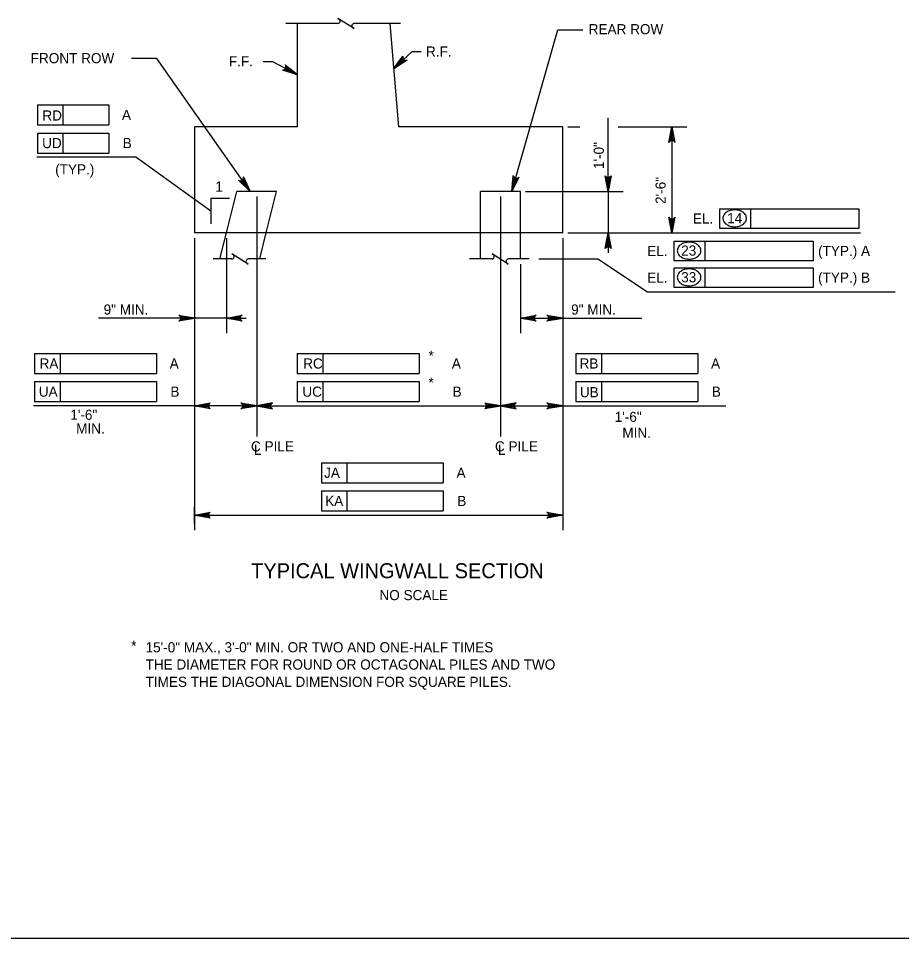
# Model space of a CAD drawing. Extents: x 638340 to 640242, y 295465 to 298435.
# Drawn here: x 639639.2 to 639900.6, y 296074.5 to 296346.9 of the extents above; entities that cross this region are included whole.
import ezdxf

# ---------------------------------------------------------------- set-up
doc = ezdxf.new("R2010")
doc.units = 0
for name, color, linetype in [('2', 7, 'Continuous'), ('4', 7, 'Continuous'), ('Level 2', 7, 'Continuous'), ('Level 4', 7, 'Continuous'), ('Level 5', 7, 'Continuous')]:
    doc.layers.add(name, color=color, linetype=linetype)

msp = doc.modelspace()

# ---------------------------------------------------------------- linework, layer by layer
at = {"layer": '2'}
msp.add_line((640102.46, 296074.46), (639316.46, 296074.46), dxfattribs=at)
at = {"layer": 'Level 2'}
for p, q in [((639798.82, 296343.48), (639806.3, 296343.48)), ((639750.26, 296331.93), (639755.72, 296337.09)), ((639755.72, 296337.09), (639758.45, 296337.09)), ((639680.15, 296334.99), (639672.65, 296334.99)), ((639714.53, 296334.05), (639711.68, 296334.05)), ((639721.87, 296330.24), (639714.53, 296334.05)), ((639644.86, 296321.27), (639665.95, 296321.27)), ((639644.86, 296321.27), (639644.86, 296315.38)), ((639652.41, 296321.27), (639652.41, 296315.38)), ((639665.95, 296321.27), (639665.95, 296315.38)), ((639644.86, 296315.38), (639665.95, 296315.38)), ((639813.74, 296295.66), (639813.74, 296317.49)), ((639644.86, 296312.93), (639644.86, 296307.04)), ((639644.86, 296312.93), (639665.95, 296312.93)), ((639652.41, 296312.93), (639652.41, 296307.04)), ((639665.95, 296312.93), (639665.95, 296307.04)), ((639801.84, 296314.82), (639805.36, 296314.82)), ((639816.72, 296314.82), (639837.05, 296314.82)), ((639832.62, 296314.82), (639832.62, 296283.39)), ((639644.86, 296307.04), (639665.95, 296307.04)), ((639673.99, 296305.77), (639644.7, 296305.77)), ((639696.17, 296289.84), (639673.99, 296305.77)), ((639696.17, 296293.58), (639696.17, 296286.1)), ((639701.71, 296293.58), (639696.17, 296293.58)), ((639709.75, 296294.13), (639709.75, 296223.13)), ((639709.75, 296294.13), (639709.75, 296223.13)), ((639781.88, 296294.13), (639781.88, 296223.13)), ((639789.31, 296295.66), (639818.16, 296295.66)), ((639813.74, 296295.66), (639813.74, 296283.39)), ((639846.84, 296290.56), (639887.97, 296290.56)), ((639846.84, 296284.66), (639846.84, 296290.56)), ((639855.99, 296284.66), (639855.99, 296290.56)), ((639887.97, 296290.56), (639887.97, 296284.66)), ((639801.84, 296283.39), (639888.44, 296283.39)), ((639801.84, 296283.39), (639818.16, 296283.39)), ((639813.74, 296283.39), (639813.74, 296277.49)), ((639887.97, 296284.66), (639846.84, 296284.66)), ((639691.35, 296281.85), (639691.35, 296219.14)), ((639691.35, 296281.85), (639691.35, 296195.4)), ((639691.35, 296281.85), (639691.35, 296253.75)), ((639700.79, 296281.85), (639700.79, 296253.75)), ((639800.3, 296281.85), (639800.3, 296219.14)), ((639800.3, 296281.85), (639800.3, 296195.4)), ((639800.3, 296281.85), (639800.3, 296253.75)), ((639833.33, 296275.08), (639833.33, 296280.97)), ((639833.33, 296280.97), (639874.46, 296280.97)), ((639842.49, 296275.08), (639842.49, 296280.97)), ((639874.46, 296280.97), (639874.46, 296275.08)), ((639787.78, 296274.13), (639787.78, 296253.75)), ((639793.26, 296275.67), (639810.7, 296275.67)), ((639810.7, 296275.67), (639825.35, 296265.91)), ((639874.46, 296275.08), (639833.33, 296275.08)), ((639833.33, 296273.08), (639874.46, 296273.08)), ((639833.33, 296267.19), (639833.33, 296273.08)), ((639842.49, 296267.19), (639842.49, 296273.08)), ((639874.46, 296273.08), (639874.46, 296267.19)), ((639874.46, 296267.19), (639833.33, 296267.19)), ((639825.35, 296265.91), (639898.72, 296265.91)), ((639700.79, 296258.17), (639662.92, 296258.17)), ((639700.79, 296258.17), (639706.68, 296258.17)), ((639787.78, 296258.17), (639800.3, 296258.17)), ((639800.3, 296258.17), (639823.7, 296258.17)), ((639644, 296247.68), (639680.07, 296247.68)), ((639644, 296247.68), (639644, 296241.79)), ((639651.55, 296247.68), (639651.55, 296241.79)), ((639680.07, 296247.68), (639680.07, 296241.79)), ((639721.76, 296247.68), (639757.82, 296247.68)), ((639721.76, 296247.68), (639721.76, 296241.79)), ((639729.3, 296247.68), (639729.3, 296241.79)), ((639757.82, 296247.68), (639757.82, 296241.79)), ((639804.21, 296247.68), (639840.27, 296247.68)), ((639804.21, 296247.68), (639804.21, 296241.79)), ((639811.75, 296247.68), (639811.75, 296241.79)), ((639840.27, 296247.68), (639840.27, 296241.79)), ((639644, 296241.79), (639680.07, 296241.79)), ((639721.76, 296241.79), (639757.82, 296241.79)), ((639804.21, 296241.79), (639840.27, 296241.79)), ((639644, 296239.35), (639680.07, 296239.35)), ((639644, 296239.35), (639644, 296233.45)), ((639651.55, 296239.35), (639651.55, 296233.45)), ((639680.07, 296239.35), (639680.07, 296233.45)), ((639721.76, 296239.35), (639757.82, 296239.35)), ((639721.76, 296239.35), (639721.76, 296233.45)), ((639729.3, 296239.35), (639729.3, 296233.45)), ((639757.82, 296239.35), (639757.82, 296233.45)), ((639800.3, 296240.69), (639800.3, 296220.6)), ((639804.21, 296239.35), (639840.27, 296239.35)), ((639804.21, 296239.35), (639804.21, 296233.45)), ((639811.75, 296239.35), (639811.75, 296233.45)), ((639840.27, 296239.35), (639840.27, 296233.45)), ((639644, 296233.45), (639680.07, 296233.45)), ((639709.75, 296235.69), (639709.75, 296227.76)), ((639721.76, 296233.45), (639757.82, 296233.45)), ((639781.88, 296235.69), (639781.88, 296227.76)), ((639804.21, 296233.45), (639840.27, 296233.45)), ((639691.35, 296232.18), (639643.74, 296232.18)), ((639706.8, 296232.18), (639691.35, 296232.18)), ((639712.7, 296232.18), (639778.94, 296232.18)), ((639784.83, 296232.18), (639800.3, 296232.18)), ((639800.3, 296232.18), (639848.6, 296232.18)), ((639728.9, 296215.32), (639764.96, 296215.32)), ((639728.9, 296215.32), (639728.9, 296209.43)), ((639736.45, 296215.32), (639736.45, 296209.43)), ((639764.96, 296215.32), (639764.96, 296209.43)), ((639728.9, 296209.43), (639764.96, 296209.43)), ((639728.9, 296206.99), (639764.96, 296206.99)), ((639728.9, 296206.99), (639728.9, 296201.1)), ((639736.45, 296206.99), (639736.45, 296201.1)), ((639764.96, 296206.99), (639764.96, 296201.1)), ((639691.35, 296197.33), (639691.35, 296202.32)), ((639728.9, 296201.1), (639764.96, 296201.1)), ((639800.3, 296202.32), (639800.3, 296197.33)), ((639691.35, 296199.82), (639800.3, 296199.82))]:
    msp.add_line(p, q, dxfattribs=at)
for points in [[(639785.22, 296295.66), (639798.82, 296343.48)], [(639707.79, 296295.66), (639680.15, 296334.99)], [(639750.26, 296331.93), (639753.04, 296335.76), (639752.95, 296335.34), (639753.03, 296334.98), (639753.21, 296334.72), (639753.46, 296334.53), (639753.81, 296334.43), (639754.24, 296334.49), (639750.26, 296331.93), (639753.81, 296334.43), (639753.46, 296334.53), (639750.26, 296331.93), (639753.21, 296334.72), (639753.03, 296334.98), (639750.26, 296331.93), (639752.95, 296335.34)], [(639721.87, 296330.24), (639717.34, 296331.61), (639717.77, 296331.67), (639718.08, 296331.86), (639718.27, 296332.11), (639718.37, 296332.41), (639718.35, 296332.77), (639718.14, 296333.16), (639721.87, 296330.24), (639718.35, 296332.77), (639718.37, 296332.41), (639721.87, 296330.24), (639718.27, 296332.11), (639718.08, 296331.86), (639721.87, 296330.24), (639717.77, 296331.67)], [(639832.62, 296314.82), (639833.5, 296310.17), (639833.25, 296310.53), (639832.94, 296310.71), (639832.62, 296310.77), (639832.31, 296310.71), (639832, 296310.53), (639831.75, 296310.17), (639832.62, 296314.82), (639832, 296310.53), (639832.31, 296310.71), (639832.62, 296314.82), (639832.62, 296310.77), (639832.94, 296310.71), (639832.62, 296314.82), (639833.25, 296310.53)], [(639707.79, 296295.66), (639704.4, 296298.96), (639704.81, 296298.81), (639705.17, 296298.84), (639705.46, 296298.98), (639705.68, 296299.2), (639705.83, 296299.53), (639705.83, 296299.97), (639707.79, 296295.66), (639705.83, 296299.53), (639705.68, 296299.2), (639707.79, 296295.66), (639705.46, 296298.98), (639705.17, 296298.84), (639707.79, 296295.66), (639704.81, 296298.81)], [(639785.22, 296295.66), (639785.65, 296300.37), (639785.8, 296299.96), (639786.05, 296299.7), (639786.33, 296299.56), (639786.65, 296299.53), (639787, 296299.62), (639787.33, 296299.9), (639785.22, 296295.66), (639787, 296299.62), (639786.65, 296299.53), (639785.22, 296295.66), (639786.33, 296299.56), (639786.05, 296299.7), (639785.22, 296295.66), (639785.8, 296299.96)], [(639813.74, 296295.66), (639812.87, 296300.31), (639813.12, 296299.95), (639813.43, 296299.77), (639813.74, 296299.71), (639814.05, 296299.77), (639814.37, 296299.95), (639814.61, 296300.31), (639813.74, 296295.66), (639814.37, 296299.95), (639814.05, 296299.77), (639813.74, 296295.66), (639813.74, 296299.71), (639813.43, 296299.77), (639813.74, 296295.66), (639813.12, 296299.95)], [(639832.62, 296283.39), (639831.75, 296288.04), (639832, 296287.68), (639832.31, 296287.49), (639832.62, 296287.44), (639832.94, 296287.49), (639833.25, 296287.68), (639833.5, 296288.04), (639832.62, 296283.39), (639833.25, 296287.68), (639832.94, 296287.49), (639832.62, 296283.39), (639832.62, 296287.44), (639832.31, 296287.49), (639832.62, 296283.39), (639832, 296287.68)], [(639813.74, 296283.39), (639814.61, 296278.73), (639814.37, 296279.09), (639814.05, 296279.28), (639813.74, 296279.33), (639813.43, 296279.28), (639813.12, 296279.09), (639812.87, 296278.73), (639813.74, 296283.39), (639813.12, 296279.09), (639813.43, 296279.28), (639813.74, 296283.39), (639813.74, 296279.33), (639814.05, 296279.28), (639813.74, 296283.39), (639814.37, 296279.09)], [(639691.35, 296258.17), (639686.7, 296257.3), (639687.06, 296257.55), (639687.25, 296257.86), (639687.3, 296258.17), (639687.25, 296258.48), (639687.06, 296258.79), (639686.7, 296259.04), (639691.35, 296258.17), (639687.06, 296258.79), (639687.25, 296258.48), (639691.35, 296258.17), (639687.3, 296258.17), (639687.25, 296257.86), (639691.35, 296258.17), (639687.06, 296257.55)], [(639700.79, 296258.17), (639705.44, 296259.04), (639705.08, 296258.79), (639704.9, 296258.48), (639704.84, 296258.17), (639704.9, 296257.86), (639705.08, 296257.55), (639705.44, 296257.3), (639700.79, 296258.17), (639705.08, 296257.55), (639704.9, 296257.86), (639700.79, 296258.17), (639704.84, 296258.17), (639704.9, 296258.48), (639700.79, 296258.17), (639705.08, 296258.79)], [(639787.78, 296258.17), (639792.43, 296259.04), (639792.07, 296258.79), (639791.89, 296258.48), (639791.83, 296258.17), (639791.89, 296257.86), (639792.07, 296257.55), (639792.43, 296257.3), (639787.78, 296258.17), (639792.07, 296257.55), (639791.89, 296257.86), (639787.78, 296258.17), (639791.83, 296258.17), (639791.89, 296258.48), (639787.78, 296258.17), (639792.07, 296258.79)], [(639800.3, 296258.17), (639795.65, 296257.3), (639796.01, 296257.55), (639796.19, 296257.86), (639796.25, 296258.17), (639796.19, 296258.48), (639796.01, 296258.79), (639795.65, 296259.04), (639800.3, 296258.17), (639796.01, 296258.79), (639796.19, 296258.48), (639800.3, 296258.17), (639796.25, 296258.17), (639796.19, 296257.86), (639800.3, 296258.17), (639796.01, 296257.55)], [(639691.35, 296232.18), (639696.01, 296233.05), (639695.65, 296232.8), (639695.46, 296232.49), (639695.41, 296232.18), (639695.46, 296231.87), (639695.65, 296231.56), (639696.01, 296231.31), (639691.35, 296232.18), (639695.65, 296231.56), (639695.46, 296231.87), (639691.35, 296232.18), (639695.41, 296232.18), (639695.46, 296232.49), (639691.35, 296232.18), (639695.65, 296232.8)], [(639709.75, 296232.18), (639705.1, 296231.31), (639705.46, 296231.56), (639705.64, 296231.87), (639705.69, 296232.18), (639705.64, 296232.49), (639705.46, 296232.8), (639705.1, 296233.05), (639709.75, 296232.18), (639705.46, 296232.8), (639705.64, 296232.49), (639709.75, 296232.18), (639705.69, 296232.18), (639705.64, 296231.87), (639709.75, 296232.18), (639705.46, 296231.56)], [(639709.75, 296232.18), (639714.4, 296231.31), (639714.04, 296231.56), (639713.86, 296231.87), (639713.8, 296232.18), (639713.86, 296232.49), (639714.04, 296232.8), (639714.4, 296233.05), (639709.75, 296232.18), (639714.04, 296232.8), (639713.86, 296232.49), (639709.75, 296232.18), (639713.8, 296232.18), (639713.86, 296231.87), (639709.75, 296232.18), (639714.04, 296231.56)], [(639781.88, 296232.18), (639777.23, 296231.31), (639777.59, 296231.56), (639777.77, 296231.87), (639777.83, 296232.18), (639777.77, 296232.49), (639777.59, 296232.8), (639777.23, 296233.05), (639781.88, 296232.18), (639777.59, 296232.8), (639777.77, 296232.49), (639781.88, 296232.18), (639777.83, 296232.18), (639777.77, 296231.87), (639781.88, 296232.18), (639777.59, 296231.56)], [(639781.88, 296232.18), (639786.53, 296231.31), (639786.18, 296231.56), (639785.99, 296231.87), (639785.94, 296232.18), (639785.99, 296232.49), (639786.18, 296232.8), (639786.53, 296233.05), (639781.88, 296232.18), (639786.18, 296232.8), (639785.99, 296232.49), (639781.88, 296232.18), (639785.94, 296232.18), (639785.99, 296231.87), (639781.88, 296232.18), (639786.18, 296231.56)], [(639800.3, 296232.18), (639795.65, 296231.31), (639796.01, 296231.56), (639796.19, 296231.87), (639796.25, 296232.18), (639796.19, 296232.49), (639796.01, 296232.8), (639795.65, 296233.05), (639800.3, 296232.18), (639796.01, 296232.8), (639796.19, 296232.49), (639800.3, 296232.18), (639796.25, 296232.18), (639796.19, 296231.87), (639800.3, 296232.18), (639796.01, 296231.56)], [(639691.35, 296199.82), (639696.01, 296200.69), (639695.65, 296200.45), (639695.46, 296200.13), (639695.41, 296199.82), (639695.46, 296199.51), (639695.65, 296199.2), (639696.01, 296198.95), (639691.35, 296199.82), (639695.65, 296199.2), (639695.46, 296199.51), (639691.35, 296199.82), (639695.41, 296199.82), (639695.46, 296200.13), (639691.35, 296199.82), (639695.65, 296200.45)], [(639800.3, 296199.82), (639795.65, 296198.95), (639796.01, 296199.2), (639796.19, 296199.51), (639796.25, 296199.82), (639796.19, 296200.13), (639796.01, 296200.45), (639795.65, 296200.69), (639800.3, 296199.82), (639796.01, 296200.45), (639796.19, 296200.13), (639800.3, 296199.82), (639796.25, 296199.82), (639796.19, 296199.51), (639800.3, 296199.82), (639796.01, 296199.2)]]:
    msp.add_lwpolyline(points, dxfattribs=at)
for points in [[(639752.74, 296333.6), (639752.07, 296334.32), (639750.26, 296331.93)], [(639719.48, 296332.04), (639719.03, 296331.16), (639721.87, 296330.24)], [(639832.13, 296311.88), (639833.12, 296311.88), (639832.62, 296314.82)], [(639707.79, 296295.66), (639706.3, 296298.21), (639705.89, 296297.93)], [(639785.22, 296295.66), (639786.27, 296298.43), (639785.79, 296298.56)], [(639813.25, 296298.61), (639814.24, 296298.61), (639813.74, 296295.66)], [(639832.13, 296286.33), (639833.12, 296286.33), (639832.62, 296283.39)], [(639813.25, 296280.44), (639814.24, 296280.44), (639813.74, 296283.39)], [(639688.41, 296258.66), (639688.41, 296257.68), (639691.35, 296258.17)], [(639703.73, 296258.66), (639703.73, 296257.68), (639700.79, 296258.17)], [(639790.72, 296258.66), (639790.72, 296257.68), (639787.78, 296258.17)], [(639797.35, 296258.66), (639797.35, 296257.68), (639800.3, 296258.17)], [(639706.8, 296232.67), (639706.8, 296231.69), (639709.75, 296232.18)], [(639712.7, 296232.67), (639712.7, 296231.69), (639709.75, 296232.18)], [(639778.94, 296232.67), (639778.94, 296231.69), (639781.88, 296232.18)], [(639784.83, 296232.67), (639784.83, 296231.69), (639781.88, 296232.18)], [(639797.35, 296232.67), (639797.35, 296231.69), (639800.3, 296232.18)]]:
    msp.add_lwpolyline(points, close=True, dxfattribs=at)
for centre, radius, start, end in [((639849.53, 296287.72), 1.82, 149.9767, 180), ((639850.34, 296287.25), 2.75, 125.6316, 149.9767), ((639850.86, 296286.52), 3.65, 106.5358, 125.6316), ((639851.21, 296285.36), 4.86, 90, 106.5358), ((639851.21, 296285.36), 4.86, 73.4642, 90), ((639851.55, 296286.52), 3.65, 54.3684, 73.4642), ((639852.08, 296287.25), 2.75, 30.0233, 54.3684), ((639852.88, 296287.72), 1.82, 0, 30.0233), ((639849.53, 296287.72), 1.82, 180, 210.0233), ((639850.34, 296288.18), 2.75, 210.0233, 234.3684), ((639850.86, 296288.92), 3.65, 234.3684, 253.4642), ((639851.21, 296290.08), 4.86, 253.4642, 270), ((639851.21, 296290.08), 4.86, 270, 286.5358), ((639851.55, 296288.92), 3.65, 286.5358, 305.6316), ((639852.08, 296288.18), 2.75, 305.6316, 329.9767), ((639852.88, 296287.72), 1.82, 329.9767, 0), ((639836.83, 296277.67), 2.75, 125.6316, 149.9767), ((639837.36, 296276.93), 3.65, 106.5358, 125.6316), ((639837.7, 296275.78), 4.86, 90, 106.5358), ((639837.7, 296275.78), 4.86, 73.4642, 90), ((639838.05, 296276.93), 3.65, 54.3684, 73.4642), ((639838.57, 296277.67), 2.75, 30.0233, 54.3684), ((639836.03, 296278.13), 1.82, 149.9767, 180), ((639836.03, 296278.13), 1.82, 180, 210.0233), ((639836.83, 296278.6), 2.75, 210.0233, 234.3684), ((639838.57, 296278.6), 2.75, 305.6316, 329.9767), ((639839.38, 296278.13), 1.82, 0, 30.0233), ((639839.38, 296278.13), 1.82, 329.9767, 0), ((639837.36, 296279.33), 3.65, 234.3684, 253.4642), ((639837.7, 296280.49), 4.86, 253.4642, 270), ((639837.7, 296280.49), 4.86, 270, 286.5358), ((639838.05, 296279.33), 3.65, 286.5358, 305.6316), ((639836.83, 296269.78), 2.75, 125.6316, 149.9767), ((639837.36, 296269.04), 3.65, 106.5358, 125.6316), ((639837.7, 296267.89), 4.86, 90, 106.5358), ((639837.7, 296267.89), 4.86, 73.4642, 90), ((639838.05, 296269.04), 3.65, 54.3684, 73.4642), ((639838.57, 296269.78), 2.75, 30.0233, 54.3684), ((639836.03, 296270.24), 1.82, 149.9767, 180), ((639836.03, 296270.24), 1.82, 180, 210.0233), ((639836.83, 296270.71), 2.75, 210.0233, 234.3684), ((639838.57, 296270.71), 2.75, 305.6316, 329.9767), ((639839.38, 296270.24), 1.82, 0, 30.0233), ((639839.38, 296270.24), 1.82, 329.9767, 0), ((639837.36, 296271.44), 3.65, 234.3684, 253.4642), ((639837.7, 296272.6), 4.86, 253.4642, 270), ((639837.7, 296272.6), 4.86, 270, 286.5358), ((639838.05, 296271.44), 3.65, 286.5358, 305.6316)]:
    msp.add_arc(centre, radius, start, end, dxfattribs=at)
at = {"layer": 'Level 4'}
for p, q in [((639733.78, 296345.39), (639718.35, 296345.39)), ((639721.87, 296314.82), (639721.87, 296345.39)), ((639752.28, 296345.39), (639738.63, 296345.39)), ((639749.14, 296345.39), (639751.69, 296314.82)), ((639691.35, 296314.82), (639691.35, 296283.39)), ((639721.87, 296314.82), (639691.35, 296314.82)), ((639800.3, 296314.82), (639751.69, 296314.82)), ((639800.3, 296283.39), (639800.3, 296314.82)), ((639800.3, 296283.39), (639691.35, 296283.39))]:
    msp.add_line(p, q, dxfattribs=at)
msp.add_lwpolyline([(639738.27, 296344.07), (639738.57, 296343.88), (639733.77, 296346.9), (639734.09, 296346.7)], dxfattribs=at)
for centre, start, end in [((639733.71, 296346.1), 275.3286, 57.8672), ((639738.62, 296344.68), 90, 240)]:
    msp.add_arc(centre, 0.709, start, end, dxfattribs=at)
at = {"layer": 'Level 5'}
for p, q in [((639700.79, 296283.39), (639703.86, 296295.66)), ((639715.64, 296295.66), (639703.86, 296295.66)), ((639712.57, 296283.39), (639715.64, 296295.66)), ((639775.99, 296283.39), (639775.99, 296295.66)), ((639787.78, 296295.66), (639775.99, 296295.66)), ((639787.78, 296283.39), (639787.78, 296295.66)), ((639698.86, 296275.67), (639700.79, 296283.39)), ((639710.65, 296275.67), (639712.57, 296283.39)), ((639775.99, 296275.67), (639775.99, 296283.39)), ((639787.78, 296275.67), (639787.78, 296283.39)), ((639702.43, 296275.67), (639696.83, 296275.67)), ((639712.45, 296275.67), (639707.27, 296275.67)), ((639779.42, 296275.67), (639772.7, 296275.67)), ((639790.4, 296275.67), (639784.27, 296275.67))]:
    msp.add_line(p, q, dxfattribs=at)
for points in [[(639706.92, 296274.34), (639707.22, 296274.16), (639702.42, 296277.18), (639702.74, 296276.98)], [(639783.91, 296274.34), (639784.21, 296274.16), (639779.41, 296277.18), (639779.73, 296276.98)]]:
    msp.add_lwpolyline(points, dxfattribs=at)
for centre, start, end in [((639702.36, 296276.37), 275.3286, 57.8672), ((639779.35, 296276.37), 275.3286, 57.8672), ((639707.27, 296274.96), 90, 240), ((639784.27, 296274.96), 90, 240)]:
    msp.add_arc(centre, 0.709, start, end, dxfattribs=at)

# ---------------------------------------------------------------- texts
at = {"layer": '2'}
msp.add_text('NO SCALE', height=3, dxfattribs=at).set_placement((639746.07, 296174.66))
at = {"layer": '4'}
msp.add_text('TYPICAL WINGWALL SECTION', height=4.4294, dxfattribs=at).set_placement((639708.1, 296181.16))
at = {"layer": 'Level 2'}
for s, height, p in [('REAR ROW', 3, (639808, 296342.21)), ('R.F.', 3, (639759.86, 296335.6)), ('FRONT ROW', 3, (639642.87, 296333.64)), ('F.F.', 3, (639701.52, 296332.69)), ('1', 3, (639697.5, 296295.62)), ('EL.', 3, (639838.84, 296286.15)), ('14', 3, (639848.97, 296286.26)), ('EL.', 3, (639825.33, 296276.56)), ('23', 3, (639835.37, 296276.67)), ('(TYP.) A', 3, (639875.88, 296276.56)), ('EL.', 3, (639825.33, 296268.67)), ('33', 3, (639835.37, 296268.78)), ('(TYP.) B', 3, (639875.88, 296268.67)), ('9" MIN.', 3, (639664.45, 296259.21)), ('9" MIN.', 3, (639802.81, 296259.21)), ('1\'-6"', 3, (639654.57, 296228.05)), ('1\'-6"', 3, (639815.68, 296227.44)), ('MIN.', 3, (639656.32, 296223.98)), ('MIN.', 3, (639817.95, 296222.73)), ('C PILE', 3, (639708.06, 296218.69)), ('L', 3, (639708.95, 296217.67)), ('C PILE', 3, (639780.26, 296218.69)), ('L', 3, (639781.14, 296217.67)), ('15\'-0" MAX., 3\'-0" MIN. OR TWO AND ONE-HALF TIMES', 3.0001, (639676.86, 296159.21)), ('THE DIAMETER FOR ROUND OR OCTAGONAL PILES AND TWO', 3.0001, (639676.86, 296154.1)), ('TIMES THE DIAGONAL DIMENSION FOR SQUARE PILES.', 3.0001, (639676.86, 296148.98))]:
    msp.add_text(s, height=height, dxfattribs=at).set_placement(p)
for s, rotation, p in [('RD', 359.9382, (639646.32, 296316.66)), ('A', 359.9382, (639669.88, 296316.82)), ('UD', 359.9382, (639646.25, 296308.49)), ('B', 359.9382, (639670.1, 296308.49)), ('1\'-0"', 90, (639812.49, 296302.29)), ('(TYP.)', 359.9382, (639650.11, 296300.71)), ('2\'-6"', 90, (639830.78, 296291.97)), ('*', 359.9382, (639760.59, 296245.53)), ('RA', 359.9382, (639645.49, 296243.24)), ('A', 359.9382, (639684, 296243.24)), ('RC', 359.9382, (639723.5, 296243.24)), ('A', 359.9382, (639767.5, 296243.24)), ('RB', 359.9382, (639805.29, 296243.24)), ('A', 359.9382, (639844.2, 296243.24)), ('*', 359.9382, (639760.59, 296237.58)), ('UA', 359.9382, (639645.26, 296234.9)), ('B', 359.9382, (639684.22, 296234.9)), ('UC', 359.9382, (639723.27, 296234.9)), ('B', 359.9382, (639767.72, 296234.9)), ('UB', 359.9382, (639805.39, 296234.74)), ('B', 359.9382, (639844.43, 296234.9)), ('JA', 359.9382, (639729.68, 296210.88)), ('A', 359.9382, (639768.89, 296210.88)), ('KA', 359.9382, (639730.01, 296202.55)), ('B', 359.9382, (639769.12, 296202.54)), ('*', 359.9382, (639672.6, 296159.63))]:
    msp.add_text(s, height=3, rotation=rotation, dxfattribs=at).set_placement(p)

doc.saveas('drawing.dxf')
